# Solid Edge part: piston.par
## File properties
Author: Deepak Maini
Template: normal.par
Last saved by: Robert a Rhodes jr
Revision: 8
Application: Solid Edge
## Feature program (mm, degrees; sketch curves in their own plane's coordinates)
sketch for "unnamed RevolvedProtrusion 1" plane through (0, 0, 0) normal (0, -1, 0) x-axis (1, 0, 0)
  line (0, 27.2252) -> (0, 16)
  line (0, 16) -> (37, 16)
  line (37, 16) -> (37, -4)
  line (37, -4) -> (38.5, -4)
  line (38.5, -4) -> (38.5, -34)
  line (38.5, -34) -> (37, -34)
  line (37, -34) -> (37, -46)
  line (46.5, -46) -> (37, -46)
  line (46.5, -41) -> (46.5, -46)
  line (42.5, -41) -> (46.5, -41)
  line (42.5, -39) -> (42.5, -41)
  line (46.5, -39) -> (42.5, -39)
  line (46.5, 0) -> (46.5, -39)
  line (42.5, 0) -> (46.5, 0)
  line (42.5, 3) -> (42.5, 0)
  line (46.5, 3) -> (42.5, 3)
  line (46.5, 5) -> (46.5, 3)
  line (42.5, 5) -> (46.5, 5)
  line (42.5, 8) -> (42.5, 5)
  line (46.5, 8) -> (42.5, 8)
  line (46.5, 10) -> (46.5, 8)
  line (42.5, 10) -> (46.5, 10)
  line (42.5, 13) -> (42.5, 10)
  line (46.5, 13) -> (42.5, 13)
  line (46.5, 15) -> (46.5, 13)
  line (42.5, 15) -> (46.5, 15)
  line (42.5, 18) -> (42.5, 15)
  line (46.5, 18) -> (42.5, 18)
  line (46.5, 20) -> (46.5, 18)
  arc centre (-5.5431, -161.6935) radius 189 from (0, 27.2252) to (46.5, 20) cw
revolve "unnamed RevolvedProtrusion 1" add full turn 360 deg
sketch for "unnamed Protrusion 1" plane through (0, 25, 0) normal (0, -1, 0) x-axis (1, 0, 0)
  circle centre (0, -19.5) radius 19
extrude "unnamed Protrusion 1" add through along -normal
mirror "unnamed Mirror 1" of "unnamed Protrusion 1" about plane through (0, 0, 0) normal (0, -1, 0)
extrude "unnamed Protrusion 2" add through
sketch for "unnamed RevolvedCutout 1" plane through (0, 0, 0) normal (1, 0, 0) x-axis (0, 1, 0)
revolve "unnamed RevolvedCutout 1" cut finite 360 deg about sketch line (-52.4217, -19) -> (59.5434, -19)
mirror "unnamed Mirror 2" of "unnamed RevolvedCutout 1"
pattern "unnamed Pattern 1"
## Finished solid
Body 1: solid body, 42 faces, 58 edges, 16 vertices.
  Faces by surface: cylinder 21, plane 20, torus 1
  Edges by curve: circle 40, intersection 10, line 8
Bounding box of the edges (mm; curved faces can reach further): 93.000 x 93.000 x 66.000, from (-46.5, -46.5, -46) to (46.5, 46.5, 20).
Cylindrical faces by radius (mm): R10 x2, R15 x2, R19 x2, R37 x2, R38.5 x2, R42.5 x5, R46.5 x6
Toroidal faces (ring radius, tube radius in mm): R-5.5431 r189 x1
Planar faces by outward normal: +y 2, +z 7, -y 2, -z 9
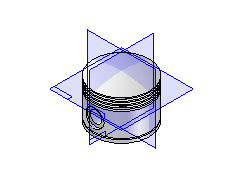
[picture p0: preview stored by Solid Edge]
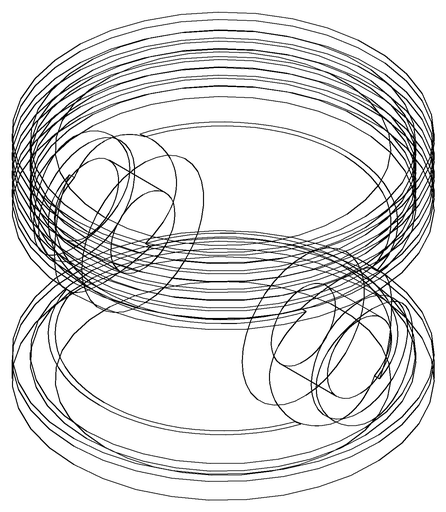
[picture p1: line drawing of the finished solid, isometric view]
